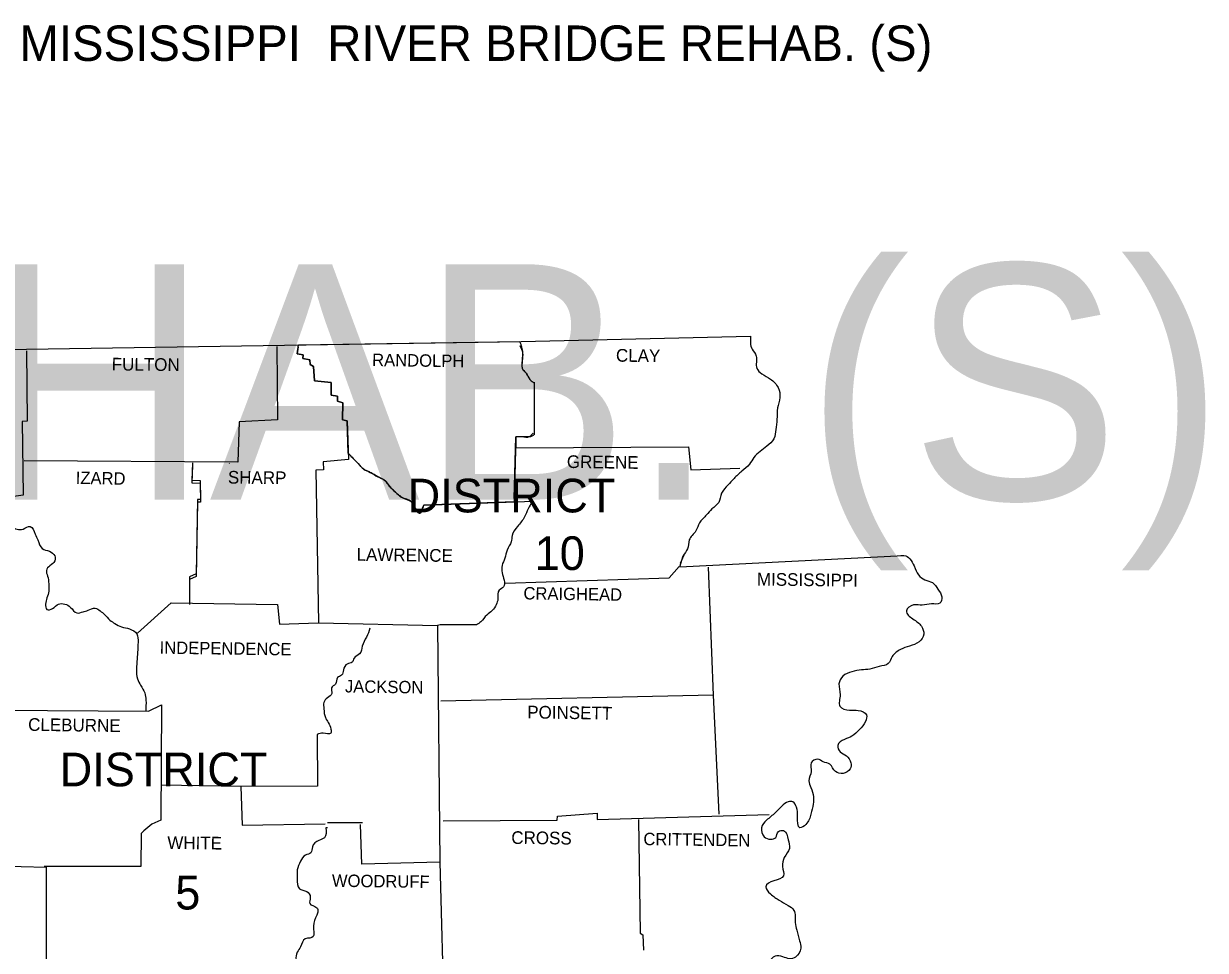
# Model space of a CAD drawing. Extents: x -712 to 3943, y 73 to 2823.
# Drawn here: x 2999.8 to 3391, y 1757.5 to 2064.5 of the extents above; entities that cross this region are included whole.
import ezdxf

# ---------------------------------------------------------------- set-up
doc = ezdxf.new("R2010")
doc.units = 0
for name, color, linetype in [('1', 7, 'Continuous'), ('2', 7, 'Continuous'), ('3', 7, 'Continuous'), ('R_Border', 7, 'Continuous')]:
    doc.layers.add(name, color=color, linetype=linetype)

msp = doc.modelspace()

# ---------------------------------------------------------------- linework, layer by layer
at = {"layer": '1'}
for p, q in [((3090.74, 1958.01), (3163.96, 1959.15)), ((3168.84, 1945.36), (3168.84, 1928.38)), ((3216.98, 1884.51), (3218.15, 1888.13)), ((3217.27, 1885.68), (3218.45, 1888.52)), ((3100.35, 1799.78), (3112, 1799.78))]:
    msp.add_line(p, q, dxfattribs=at)
for points in [[(2703.71, 1956.42), (2861.92, 1956.32), (3000.75, 1956.61), (3164.54, 1959.16), (3240.46, 1960.92)], [(3083.62, 1957.49), (3083.82, 1933.23), (3071.1, 1932.55), (3070.71, 1919.24), (2999.97, 1919.63)], [(3107.24, 1922.16), (3106.91, 1932.94), (3105.34, 1933.23), (3105.44, 1938.9), (3103.68, 1939.39), (3103.68, 1941.06), (3101.63, 1941.35), (3101.63, 1945.56), (3096.05, 1946.15), (3095.75, 1950.84), (3094.68, 1951.53), (3094.48, 1953.09), (3092.23, 1953.58), (3092.33, 1954.76), (3090.37, 1955.05), (3090.74, 1958.01)], [(3090.67, 1957.4), (3090.37, 1955.05), (3092.33, 1954.76), (3092.23, 1953.58), (3094.48, 1953.09), (3094.68, 1951.53), (3095.75, 1950.84), (3096.05, 1946.15), (3101.63, 1945.56), (3101.63, 1941.35), (3103.68, 1941.06), (3103.68, 1939.39), (3105.44, 1938.9), (3105.34, 1933.23), (3106.91, 1932.94), (3107.3, 1920.12), (3098.98, 1919.34), (3099.08, 1916.6), (3096.54, 1916.5), (3097.42, 1866.01), (3136.85, 1865.13), (3137.53, 1786.66), (3111.8, 1785.98), (3111.31, 1799.19)], [(3000.75, 1956.03), (3000.95, 1932.74), (2999.28, 1932.64), (2999.58, 1908.28), (2992.73, 1907.3), (2993.32, 1900.75), (2995.66, 1897.71), (2995.47, 1889.98), (2982.16, 1889.5), (2981.67, 1877.56), (2969.54, 1877.17), (2968.95, 1862.69), (2969.64, 1861.51), (2969.93, 1838.42), (2990.87, 1837.05), (2990.58, 1785.49), (3007.21, 1785), (3007.21, 1732.56), (2994.1, 1731.58), (2993.12, 1720.04), (2971.11, 1719.94)], [(3168.84, 1945.66), (3168.84, 1929.12)], [(3162.68, 1927.56), (3162.16, 1906), (3132.25, 1904.95)], [(3162.19, 1907.11), (3162.68, 1927.56), (3162.68, 1923.94), (3219.91, 1924.23), (3220.7, 1916.6), (3236.84, 1917.18)], [(3055.64, 1918.95), (3055.44, 1913.27), (3058.18, 1913.07), (3058.28, 1906.81), (3057.3, 1906.81), (3056.91, 1882.16), (3054.66, 1881.18), (3054.66, 1872.96)], [(3055.64, 1918.06), (3055.44, 1912.39), (3058.18, 1912.19), (3058.28, 1905.93), (3057.3, 1905.93), (3056.91, 1881.28), (3054.66, 1880.3), (3054.66, 1872.08)], [(3067.87, 1918.75), (3067.97, 1918.85)], [(3132.25, 1904.95), (3168.55, 1906.23)], [(3216.98, 1884.51), (3291.24, 1888.32)], [(3159.25, 1879.12), (3213.55, 1880.89), (3216.78, 1884.6)], [(3226.37, 1884.41), (3228.04, 1842.04), (3229.99, 1802.61)], [(3037.44, 1862.49), (3048.6, 1872.57), (3083.82, 1872.08), (3084.5, 1865.52), (3097.32, 1866.01)], [(3149.67, 1865.33), (3137.73, 1865.33), (3136.85, 1865.13)], [(3228.04, 1842.04), (3137.92, 1839.99)], [(2990.87, 1837.05), (3041.16, 1836.76), (3045.46, 1838.81), (3045.17, 1800.56), (3042.24, 1799.29), (3039.59, 1797.04), (3038.71, 1796.16), (3038.62, 1785.2), (3006.62, 1785.2)], [(3096.93, 1829.03), (3097.12, 1811.81), (3071.69, 1811.71), (3045.56, 1812.2)], [(3071.69, 1811.71), (3072.08, 1798.89), (3099.57, 1799.38)], [(3138.71, 1800.36), (3176.47, 1800.56), (3176.57, 1801.93), (3189.68, 1802.91), (3189.68, 1800.85), (3246.63, 1802.42)], [(3203.38, 1800.85), (3203.87, 1763.18), (3204.75, 1762.6), (3205.04, 1757.51)], [(3100.35, 1798.11), (3099.86, 1798.01)], [(3137.53, 1786.66), (3139, 1733.05), (3115.71, 1732.95), (3115.62, 1730.8), (3108.87, 1730.41), (3108.28, 1719.25), (3100.06, 1719.25)]]:
    msp.add_lwpolyline(points, dxfattribs=at)
for points in [[(3240.46, 1960.92), (3240.95, 1956.61), (3242.32, 1954.36), (3242.52, 1950.25), (3244.18, 1948.49), (3247.02, 1946.73), (3249.56, 1943.89), (3250.15, 1940.57), (3249.36, 1937.14), (3249.17, 1933.33), (3248.78, 1930), (3248.19, 1926.97), (3245.84, 1924.52), (3243.59, 1922.76), (3241.54, 1920.71), (3240.07, 1918.55), (3237.53, 1916.21), (3234.98, 1913.76), (3232.93, 1911.61), (3230.87, 1908.87), (3229.89, 1905.83), (3227.64, 1903.68), (3225.88, 1901.73), (3223.53, 1899.08), (3222.36, 1896.44), (3220.11, 1893.41), (3219.62, 1890.47), (3218.15, 1888.13), (3218.06, 1887.73)], [(3163.96, 1959.15), (3164.16, 1958.7), (3164.34, 1958.24), (3164.65, 1957.32), (3164.85, 1956.38), (3164.88, 1956.15), (3164.91, 1955.91), (3164.93, 1955.44), (3164.92, 1954.78), (3164.89, 1954.12), (3164.85, 1953.46), (3164.83, 1952.8), (3164.82, 1952.49), (3164.77, 1951.57), (3164.76, 1950.96), (3164.78, 1950.66), (3164.8, 1950.5), (3164.82, 1950.43), (3164.83, 1950.35), (3164.91, 1950.11), (3164.96, 1949.99), (3165.03, 1949.88), (3165.19, 1949.67), (3165.37, 1949.48), (3165.76, 1949.09), (3165.94, 1948.9), (3166.1, 1948.69), (3166.42, 1948.18), (3166.72, 1947.66), (3167.03, 1947.14), (3167.2, 1946.88), (3167.37, 1946.63), (3167.59, 1946.39), (3167.83, 1946.16), (3168.08, 1945.96), (3168.84, 1945.36)], [(3164.05, 1957.89), (3164.93, 1955.44), (3164.83, 1952.8), (3164.83, 1950.35), (3166.1, 1948.69), (3167.37, 1946.63), (3168.35, 1945.75)], [(3168.45, 1928.83), (3167.18, 1927.56), (3164.73, 1927.56), (3162.68, 1927.56)], [(3168.84, 1928.38), (3168.66, 1928.21), (3168.47, 1928.05), (3168.07, 1927.79), (3167.63, 1927.62), (3167.41, 1927.57), (3167.29, 1927.56), (3167.18, 1927.56), (3164.73, 1927.56), (3162.68, 1927.56)], [(3132.25, 1904.95), (3132.1, 1904.53), (3131.93, 1904.04), (3131.55, 1903.06), (3131.12, 1902.36), (3130.9, 1902.23), (3130.79, 1902.24), (3130.68, 1902.31), (3130.64, 1902.35), (3130.59, 1902.4), (3130.5, 1902.5), (3130.32, 1902.72), (3129.95, 1903.24), (3129.58, 1903.81), (3129.4, 1904.1), (3129.22, 1904.37), (3128.95, 1904.79), (3128.69, 1905.21), (3128.43, 1905.63), (3128.14, 1906.03), (3127.82, 1906.34), (3127.45, 1906.57), (3126.6, 1906.9), (3125.71, 1907.18), (3124.91, 1907.6), (3124.39, 1907.99), (3123.86, 1908.4), (3123.35, 1908.82), (3122.86, 1909.26), (3121.81, 1910.27), (3120.8, 1911.31), (3120.61, 1911.54), (3120.44, 1911.78), (3120.11, 1912.29), (3119.77, 1912.77), (3119.33, 1913.17), (3119.2, 1913.26), (3119.06, 1913.34), (3118.22, 1913.78), (3117.65, 1914.05), (3117.08, 1914.35), (3115.81, 1915.08), (3114.54, 1915.81), (3114, 1916.08), (3113.44, 1916.31), (3112.89, 1916.56), (3112.39, 1916.89), (3112.26, 1917), (3112.14, 1917.11), (3111.9, 1917.33), (3111.44, 1917.8), (3110.53, 1918.75), (3108.87, 1920.44), (3107.24, 1922.16)], [(3108.38, 1921), (3110.53, 1918.75), (3112.39, 1916.89), (3114.54, 1915.81), (3117.08, 1914.35), (3119.33, 1913.17), (3120.8, 1911.31), (3122.86, 1909.26), (3124.91, 1907.6), (3128.14, 1906.03), (3129.22, 1904.37), (3130.68, 1902.31), (3132.25, 1904.95)], [(3168.25, 1906.13), (3166.79, 1903.78), (3165.61, 1901.04), (3163.26, 1897.91), (3161.5, 1894.88), (3161.21, 1892.82), (3159.84, 1890.08), (3159.06, 1887.34), (3158.18, 1884.99), (3158.18, 1882.55), (3158.86, 1880.1), (3158.67, 1877.85), (3157.2, 1876.78), (3156.81, 1873.94), (3156.22, 1871.98), (3154.95, 1870.03), (3153.09, 1868.56), (3151.13, 1866.31), (3149.67, 1865.33)], [(2995.66, 1897.71), (2999.58, 1897.03), (3001.93, 1897.91), (3003.59, 1895.37), (3004.47, 1893.41), (3005.94, 1890.57), (3008.29, 1889.69), (3010.05, 1888.13), (3010.05, 1886.46), (3008.48, 1884.9), (3007.31, 1883.33), (3007.7, 1881.47), (3008.09, 1878.93), (3008.09, 1876.48), (3007.5, 1874.23), (3007.01, 1872.18), (3007.5, 1870.42), (3009.36, 1870.71), (3011.32, 1872.18), (3013.37, 1872.18), (3015.33, 1871.1), (3017.38, 1869.24), (3019.44, 1869.63), (3021.1, 1870.12), (3023.45, 1870.81), (3025.11, 1869.93), (3026.58, 1868.75), (3028.34, 1866.89), (3030.01, 1865.72), (3032.16, 1864.64), (3034.8, 1863.96), (3037.25, 1862.3), (3037.64, 1859.46), (3037.54, 1857.01), (3037.34, 1853.98), (3037.15, 1850.65), (3037.44, 1847.42), (3038.52, 1845.27), (3039.89, 1842.73), (3040.28, 1840.38), (3040.18, 1836.66)], [(3290.16, 1888.22), (3291.24, 1888.32), (3294.57, 1884.8), (3296.03, 1881.86), (3298.19, 1880.2), (3300.63, 1879.32), (3302.49, 1877.07), (3303.76, 1874.62), (3303.08, 1872.47), (3300.34, 1872.28), (3297.31, 1871.79), (3294.37, 1871.88), (3292.02, 1869.93), (3294.18, 1867.29), (3297.01, 1864.84), (3297.8, 1862.2), (3296.23, 1859.65), (3293.1, 1858.28), (3290.07, 1857.11), (3287.33, 1854.76), (3286.05, 1852.51), (3283.02, 1851.53), (3279.89, 1850.65), (3277.15, 1850.36), (3274.02, 1849.77), (3270.99, 1848.3), (3269.72, 1845.76), (3270.11, 1842.14), (3270.01, 1838.32), (3273.24, 1837.05), (3276.08, 1836.95), (3278.81, 1835.49), (3278.52, 1833.33), (3276.47, 1830.6), (3274.02, 1828.44), (3271.57, 1827.37), (3269.32, 1825.31), (3270.11, 1823.26), (3272.16, 1821.89), (3273.63, 1819.64), (3273.43, 1817.58), (3271.09, 1816.11), (3268.54, 1816.7), (3266.68, 1819.15), (3264.53, 1819.93), (3262.67, 1820.81), (3260.52, 1819.54), (3260.52, 1816.7), (3259.74, 1813.67), (3260.42, 1811.42), (3261.3, 1808.29), (3261.2, 1805.94), (3260.42, 1802.61), (3258.76, 1799.19), (3256.8, 1798.11), (3256.02, 1801.83), (3255.63, 1804.86), (3254.45, 1806.62), (3252.89, 1806.72), (3250.83, 1805.25), (3248.58, 1803), (3245.74, 1800.56), (3244.08, 1798.11), (3244.96, 1795.08), (3247.11, 1794.3), (3248.78, 1794.88), (3249.66, 1796.84), (3251.32, 1797.13), (3252.89, 1794.1)], [(3114.44, 1864.25), (3113.27, 1861.22), (3111.9, 1858.28), (3111.02, 1855.74), (3109.16, 1854.27), (3108.57, 1852.9), (3106.91, 1852.32), (3105.64, 1850.36), (3105.05, 1848.6), (3103.68, 1847.82), (3103, 1845.66), (3101.72, 1844.49), (3101.82, 1842.53), (3100.35, 1841.16), (3099.18, 1839.6), (3099.18, 1837.44), (3099.67, 1834.61), (3100.65, 1832.94), (3101.53, 1830.79), (3101.43, 1829.42), (3098.98, 1829.42), (3096.93, 1829.03)], [(3099.86, 1798.01), (3099.37, 1794.79), (3097.52, 1793.91), (3095.36, 1791.75), (3094.87, 1789.8), (3093.11, 1789.01), (3091.45, 1786.96), (3090.37, 1784.12), (3090.37, 1781.19), (3091.06, 1777.86), (3093.5, 1776.98), (3094.68, 1775.02), (3094.48, 1772.97), (3096.83, 1771.6), (3097.22, 1770.42), (3096.83, 1769.15), (3095.75, 1765.53), (3095.85, 1763.09), (3095.66, 1762.01), (3093.02, 1761.32), (3091.45, 1758.68), (3090.37, 1756.82), (3089.98, 1754.38), (3090.28, 1752.62), (3089.49, 1751.25), (3089.2, 1749.19), (3088.22, 1747.43), (3087.34, 1745.77), (3088.32, 1743.81), (3088.03, 1742.44), (3087.44, 1740.29), (3087.93, 1739.6)], [(3252.89, 1794.1), (3253.28, 1791.26), (3251.62, 1788.23), (3251.03, 1785.2), (3251.32, 1782.16), (3248.19, 1780.5), (3245.45, 1778.54), (3247.02, 1776.2), (3249.95, 1774.04), (3252.89, 1772.38), (3254.75, 1770.72), (3255.24, 1766.71), (3255.72, 1764.16), (3256.7, 1760.64), (3257.09, 1758.19), (3255.33, 1755.26), (3253.28, 1754.67), (3251.13, 1755.36), (3248.58, 1755.55), (3246.53, 1753.59), (3245.06, 1750.86), (3243.59, 1748.12), (3242.52, 1745.77), (3241.44, 1743.22), (3239.29, 1740.29), (3236.65, 1739.8), (3233.51, 1739.02), (3231.66, 1736.86), (3231.95, 1733.24), (3233.71, 1730.8), (3235.08, 1727.76), (3236.06, 1725.12), (3235.57, 1721.8), (3234.2, 1719.35), (3232.44, 1717.88), (3231.66, 1714.75), (3230.38, 1712.4), (3229.21, 1711.62), (3226.86, 1711.82), (3224.32, 1712.31), (3222.16, 1712.11), (3220.11, 1711.03), (3218.06, 1711.72), (3215.9, 1714.07), (3214.14, 1715.83), (3212.19, 1716.51), (3210.13, 1715.44), (3209.74, 1712.21), (3210.72, 1708.88), (3211.6, 1704.38), (3210.72, 1701.64), (3210.42, 1697.14)]]:
    msp.add_spline(points, degree=3, dxfattribs=at)

# ---------------------------------------------------------------- texts
at = {"layer": '2'}
msp.add_text('HWY. 49 MISSISSIPPI RIVER BRIDGE REHAB. (S)', height=78, dxfattribs=at).set_placement((969, 1906.78))
for s, height, rotation, p in [('CLAY', 4.206, 359.2258, (3195.85, 1952.5)), ('FULTON', 4.206, 359.4996, (3028.93, 1949.57)), ('RANDOLPH', 4.109, 359.2583, (3115.13, 1951.04)), ('GREENE', 4.207, 359.2361, (3179.6, 1917.28)), ('IZARD', 4.108, 358.9258, (3016.99, 1912)), ('SHARP', 4.206, 359.3905, (3067.38, 1912.1)), ('LAWRENCE', 4.207, 359.2678, (3109.98, 1886.54)), ('MISSISSIPPI', 4.2062, 359.3097, (3242.52, 1878.34)), ('CRAIGHEAD', 4.109, 359.1159, (3165.22, 1873.74)), ('INDEPENDENCE', 4.1081, 359.2187, (3044.78, 1855.74)), ('JACKSON', 4.108, 359.1352, (3106.13, 1842.92)), ('POINSETT', 4.206, 359.1987, (3166.49, 1834.31)), ('CLEBURNE', 4.206, 359.2535, (3001.24, 1830.2)), ('CROSS', 4.206, 359.3839, (3161.21, 1792.73)), ('CRITTENDEN', 4.109, 359.213, (3204.94, 1792.34)), ('WHITE', 4.207, 359.3139, (3047.32, 1791.07)), ('WOODRUFF', 4.108, 359.2748, (3101.82, 1778.54))]:
    msp.add_text(s, height=height, rotation=rotation, dxfattribs=at).set_placement(p)
at = {"layer": '3'}
for s, height, p in [('DISTRICT', 11.154, (3126.9, 1902.55)), ('10', 11.154, (3168.97, 1883.47)), ('DISTRICT', 11.154, (3011.71, 1811.81)), ('5', 11.15, (3049.97, 1771.01))]:
    msp.add_text(s, height=height, dxfattribs=at).set_placement(p)
at = {"layer": 'R_Border'}
msp.add_text('HWY. 49 MISSISSIPPI  RIVER BRIDGE REHAB. (S)', height=11.724, dxfattribs=at).set_placement((2931.28, 2052.13))

doc.saveas('drawing.dxf')
